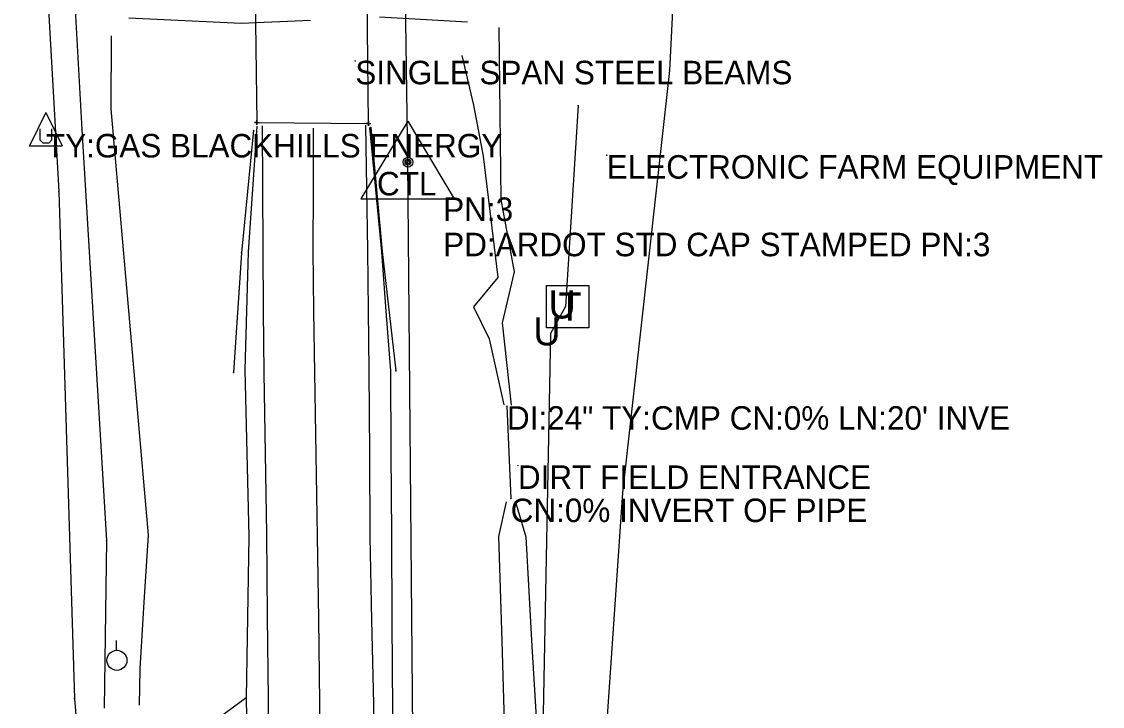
# Model space of a CAD drawing. Extents: x 1804576 to 1805329, y 515859 to 519427.
# Drawn here: x 1804889.4 to 1805119.1, y 517586 to 517731.6 of the extents above; entities that cross this region are included whole.
import ezdxf

# ---------------------------------------------------------------- set-up
doc = ezdxf.new("R2010")
doc.units = 0
for name, color, linetype in [('Default', 7, 'Continuous'), ('S_BASELINE', 7, 'Continuous'), ('S_BRIDGE', 7, 'Continuous'), ('S_DITCHLINE', 7, 'Continuous'), ('S_DRG_PT_SYM', 7, 'Continuous'), ('S_EDGE_PAVEMENT', 7, 'Continuous'), ('S_FIBER_OPTIC_CABLE', 7, 'Continuous'), ('S_GAS_UTILITIES', 7, 'Continuous'), ('S_GUARDRAIL', 7, 'Continuous'), ('S_MISC_STRUCTURES_ANNOT', 7, 'Continuous'), ('S_MSC_PT_SYM', 7, 'Continuous'), ('S_PAVEMENT_CROWN', 7, 'Continuous'), ('S_PRIMARY_CTL', 7, 'Continuous'), ('S_PRIMARY_CTL_ANNOT', 7, 'Continuous'), ('S_RDW_PT_SYM', 7, 'Continuous'), ('S_SHOULDER', 7, 'Continuous'), ('S_SIDE_DRAIN', 7, 'Continuous'), ('S_SIDE_DRAIN_ANNOT', 7, 'Continuous'), ('S_STR_PT_SYM', 7, 'Continuous'), ('S_STREAM', 7, 'Continuous'), ('S_SURVEY_TEXT_ANNOT', 7, 'Continuous'), ('S_TELEPHONE_UTILITIES', 7, 'Continuous'), ('S_UNDERGROUND_CABLE', 7, 'Continuous'), ('S_UTILITY_POLE', 7, 'Continuous'), ('S_UTILITY_POLE_ANNOT', 7, 'Continuous'), ('S_UTL_PT_SYM', 7, 'Continuous'), ('S_WATER_UTILITIES', 7, 'Continuous')]:
    doc.layers.add(name, color=color, linetype=linetype)

msp = doc.modelspace()

# ---------------------------------------------------------------- linework, layer by layer
at = {"layer": 'S_BASELINE'}
for p, q in [((1804971.48, 517701.71), (1804956.7, 518650.01)), ((1804979.02, 516850.02), (1804971.48, 517701.71))]:
    msp.add_line(p, q, dxfattribs=at)
at = {"layer": 'S_BRIDGE'}
for p, q in [((1804963.12, 517709.92), (1804962.51, 517765.12)), ((1804938.7, 517764.9), (1804939.34, 517710.14)), ((1804939.34, 517710.14), (1804963.12, 517709.92))]:
    msp.add_line(p, q, dxfattribs=at)
at = {"layer": 'S_DITCHLINE'}
for points in [[(1804908.38, 517728.61), (1804908.3, 517713.03), (1804910.28, 517690.37), (1804912.27, 517667.7), (1804914.25, 517645.04), (1804916.23, 517622.38), (1804915.35, 517608.16), (1804914.48, 517593.93), (1804914.34, 517586.26)], [(1804993.51, 517650.05), (1804991.59, 517667.58), (1804994.15, 517678.37), (1804991.29, 517693.8), (1804991.07, 517712.08), (1804990.84, 517730.36)], [(1804982.94, 517724.38), (1804985.41, 517713.87), (1804987.46, 517703.03), (1804989.02, 517690.1), (1804990.58, 517677.17), (1804985.38, 517670.95), (1804988.71, 517664.18), (1804991.88, 517650.09)], [(1804992.34, 517629.48), (1804990.73, 517622.13), (1804991.4, 517599.91), (1804992.07, 517577.69), (1804991.26, 517563.34), (1804990.45, 517548.98), (1804989.64, 517534.63), (1804988.82, 517520.28), (1804988.18, 517498.42), (1804987.54, 517476.57), (1804986.98, 517462.63), (1804986.42, 517448.7), (1804985.86, 517434.77), (1804985.31, 517420.83), (1804985.82, 517401.34), (1804986.33, 517381.85)], [(1804994.29, 517629.66), (1804996.5, 517622.01), (1804997.84, 517598.75), (1804999.19, 517575.49), (1804996.83, 517561.75), (1804994.47, 517548), (1804992.11, 517534.26), (1804989.75, 517520.52), (1804988.99, 517498.56), (1804988.23, 517476.6), (1804987.73, 517462.59), (1804987.24, 517448.59), (1804986.75, 517434.59), (1804986.25, 517420.59), (1804986.64, 517401.2), (1804987.03, 517381.82)]]:
    msp.add_lwpolyline(points, dxfattribs=at)
at = {"layer": 'S_DRG_PT_SYM'}
for points in [[(1804992.52, 517649.82), (1804992.52, 517649.87), (1804992.52, 517649.82), (1804992.47, 517649.82), (1804992.52, 517649.82), (1804992.52, 517649.77), (1804992.52, 517649.82), (1804992.57, 517649.82)], [(1804993.31, 517630.17), (1804993.31, 517630.22), (1804993.31, 517630.17), (1804993.26, 517630.17), (1804993.31, 517630.17), (1804993.31, 517630.12), (1804993.31, 517630.17), (1804993.36, 517630.17)]]:
    msp.add_lwpolyline(points, dxfattribs=at)
at = {"layer": 'S_EDGE_PAVEMENT'}
for points in [[(1804940.46, 517709.42), (1804940.53, 517696.33), (1804940.61, 517683.24), (1804940.74, 517670.08), (1804940.88, 517656.93), (1804941.15, 517639.79), (1804941.42, 517622.66), (1804941.59, 517605.09), (1804941.76, 517587.51), (1804941.82, 517574.8), (1804941.89, 517562.09), (1804942.21, 517539.1), (1804942.54, 517516.11), (1804942.97, 517492.9), (1804943.39, 517469.69), (1804943.57, 517445.12), (1804943.76, 517420.54), (1804944.11, 517396.98), (1804944.47, 517373.41)], [(1804962.48, 517709.57), (1804962.67, 517696.25), (1804962.86, 517682.93), (1804963.02, 517670.14), (1804963.19, 517657.36), (1804963.3, 517639.71), (1804963.4, 517622.06), (1804963.76, 517604.29), (1804964.12, 517586.52), (1804964.31, 517564.57), (1804964.38, 517544.75), (1804964.45, 517524.93), (1804964.7, 517511.48), (1804964.95, 517498.03), (1804965.2, 517484.58), (1804965.45, 517471.12), (1804965.58, 517458.56), (1804965.7, 517445.99), (1804965.83, 517433.42), (1804965.96, 517420.85), (1804966.31, 517397.71), (1804966.66, 517374.58)], [(1804937.12, 517587.77), (1804929.82, 517582.39), (1804921.73, 517579.49), (1804914.51, 517578.77), (1804913.22, 517568.91), (1804921.24, 517568.04), (1804930.31, 517565.67), (1804937.46, 517562.48)]]:
    msp.add_lwpolyline(points, dxfattribs=at)
at = {"layer": 'S_FIBER_OPTIC_CABLE'}
for p, q in [((1804895.93, 517822.38), (1804902.15, 517708.69)), ((1805007.68, 517713.77), (1805004.99, 517671.01)), ((1804902.15, 517708.69), (1804907.42, 517621.23)), ((1805004.99, 517671.01), (1805001.76, 517665.3)), ((1805001.76, 517665.3), (1804999.7, 517558.11)), ((1804907.42, 517621.23), (1804906.91, 517585.58))]:
    msp.add_line(p, q, dxfattribs=at)
at = {"layer": 'S_GAS_UTILITIES'}
for p, q in [((1804889.37, 517837.53), (1804897.25, 517695.47)), ((1804897.25, 517695.47), (1804900.59, 517587.64)), ((1804900.59, 517587.64), (1804907.72, 517506.16))]:
    msp.add_line(p, q, dxfattribs=at)
at = {"layer": 'S_GUARDRAIL'}
for p, q in [((1804938.68, 517708.49), (1804936.1, 517682.44)), ((1804963.58, 517709.11), (1804965.97, 517682.7)), ((1804936.1, 517682.44), (1804934.39, 517656.96)), ((1804965.97, 517682.7), (1804968.9, 517657.34))]:
    msp.add_line(p, q, dxfattribs=at)
at = {"layer": 'S_MSC_PT_SYM'}
for points in [[(1804960.29, 517723.28), (1804960.29, 517723.33), (1804960.29, 517723.28), (1804960.24, 517723.28), (1804960.29, 517723.28), (1804960.29, 517723.23), (1804960.29, 517723.28), (1804960.34, 517723.28)], [(1805013.73, 517703.21), (1805013.73, 517703.26), (1805013.73, 517703.21), (1805013.68, 517703.21), (1805013.73, 517703.21), (1805013.73, 517703.16), (1805013.73, 517703.21), (1805013.78, 517703.21)], [(1804994.85, 517637.23), (1804994.85, 517637.28), (1804994.85, 517637.23), (1804994.8, 517637.23), (1804994.85, 517637.23), (1804994.85, 517637.18), (1804994.85, 517637.23), (1804994.9, 517637.23)]]:
    msp.add_lwpolyline(points, dxfattribs=at)
at = {"layer": 'S_PAVEMENT_CROWN'}
msp.add_lwpolyline([(1804951.35, 517708.92), (1804951.32, 517696), (1804951.29, 517683.08), (1804951.43, 517670), (1804951.58, 517656.91), (1804951.88, 517639.56), (1804952.18, 517622.21), (1804952.44, 517604.51), (1804952.7, 517586.81), (1804952.87, 517563.54), (1804953.18, 517539.97), (1804953.49, 517516.4), (1804953.89, 517493.53), (1804954.28, 517470.66), (1804954.4, 517458.04), (1804954.53, 517445.43), (1804954.65, 517432.82), (1804954.78, 517420.21), (1804955.07, 517396.93), (1804955.36, 517373.65)], dxfattribs=at)
at = {"layer": 'S_PRIMARY_CTL'}
for p, q in [((1804971.48, 517710.42), (1804961.45, 517693.9)), ((1804971.48, 517710.42), (1804981.31, 517693.9)), ((1804961.45, 517693.9), (1804981.31, 517693.9))]:
    msp.add_line(p, q, dxfattribs=at)
for radius in [1.04, 0.609, 0.344]:
    msp.add_circle((1804971.48, 517701.71), radius, dxfattribs=at)
at = {"layer": 'S_RDW_PT_SYM'}
for points in [[(1804938.68, 517708.49), (1804938.68, 517708.54), (1804938.68, 517708.49), (1804938.63, 517708.49), (1804938.68, 517708.49), (1804938.68, 517708.44), (1804938.68, 517708.49), (1804938.73, 517708.49)], [(1804963.58, 517709.11), (1804963.58, 517709.16), (1804963.58, 517709.11), (1804963.53, 517709.11), (1804963.58, 517709.11), (1804963.58, 517709.06), (1804963.58, 517709.11), (1804963.63, 517709.11)], [(1804936.1, 517682.44), (1804936.1, 517682.49), (1804936.1, 517682.44), (1804936.05, 517682.44), (1804936.1, 517682.44), (1804936.1, 517682.39), (1804936.1, 517682.44), (1804936.15, 517682.44)], [(1804965.97, 517682.7), (1804965.97, 517682.75), (1804965.97, 517682.7), (1804965.92, 517682.7), (1804965.97, 517682.7), (1804965.97, 517682.65), (1804965.97, 517682.7), (1804966.02, 517682.7)], [(1804934.39, 517656.96), (1804934.39, 517657.01), (1804934.39, 517656.96), (1804934.34, 517656.96), (1804934.39, 517656.96), (1804934.39, 517656.91), (1804934.39, 517656.96), (1804934.44, 517656.96)], [(1804968.9, 517657.34), (1804968.9, 517657.39), (1804968.9, 517657.34), (1804968.85, 517657.34), (1804968.9, 517657.34), (1804968.9, 517657.29), (1804968.9, 517657.34), (1804968.95, 517657.34)]]:
    msp.add_lwpolyline(points, dxfattribs=at)
at = {"layer": 'S_SHOULDER'}
for points in [[(1804939.34, 517709.36), (1804938.44, 517696.01), (1804937.54, 517682.66), (1804937.19, 517670.12), (1804936.83, 517657.58), (1804937.23, 517639.85), (1804937.63, 517622.12), (1804937.37, 517604.95), (1804937.12, 517587.79), (1804937.29, 517575.12), (1804937.45, 517562.46), (1804938.01, 517539.37), (1804938.57, 517516.27), (1804938.84, 517492.83), (1804939.1, 517469.39), (1804939.28, 517445.13), (1804939.46, 517420.88), (1804939.67, 517396.64), (1804939.87, 517372.4)], [(1804963.34, 517709.11), (1804964.59, 517695.88), (1804965.85, 517682.65), (1804966.81, 517670), (1804967.78, 517657.34), (1804967.87, 517639.95), (1804967.96, 517622.56), (1804968.08, 517603.88), (1804968.2, 517585.21), (1804968.75, 517563.81), (1804969, 517539.98), (1804969.26, 517516.16), (1804969.52, 517493.79), (1804969.79, 517471.42), (1804969.98, 517458.76), (1804970.17, 517446.09), (1804970.36, 517433.42), (1804970.55, 517420.76), (1804970.85, 517398.22), (1804971.15, 517375.69)]]:
    msp.add_lwpolyline(points, dxfattribs=at)
at = {"layer": 'S_SIDE_DRAIN'}
msp.add_line((1804992.52, 517649.82), (1804993.31, 517630.17), dxfattribs=at)
at = {"layer": 'S_STR_PT_SYM'}
for points in [[(1804939.34, 517710.14), (1804939.34, 517710.64), (1804939.34, 517710.14), (1804938.84, 517710.14), (1804939.34, 517710.14), (1804939.34, 517709.64), (1804939.34, 517710.14), (1804939.84, 517710.14)], [(1804963.12, 517709.92), (1804963.12, 517710.42), (1804963.12, 517709.92), (1804962.62, 517709.92), (1804963.12, 517709.92), (1804963.12, 517709.42), (1804963.12, 517709.92), (1804963.62, 517709.92)]]:
    msp.add_lwpolyline(points, dxfattribs=at)
at = {"layer": 'S_STREAM'}
for points in [[(1804950.73, 517731.88), (1804936.03, 517731.18), (1804912.17, 517732.34)], [(1804984.11, 517731.52), (1804965.43, 517732.59)]]:
    msp.add_lwpolyline(points, dxfattribs=at)
at = {"layer": 'S_TELEPHONE_UTILITIES'}
msp.add_lwpolyline([(1805000.89, 517666.52), (1805000.89, 517675.52), (1805009.89, 517675.52), (1805009.89, 517666.52)], close=True, dxfattribs=at)
at = {"layer": 'S_UNDERGROUND_CABLE'}
for p, q in [((1804894.54, 517712.25), (1804891.01, 517705.16)), ((1804894.54, 517712.25), (1804898.02, 517705.16)), ((1804893.34, 517706.4), (1804893.34, 517708.84)), ((1804895.7, 517708.84), (1804895.7, 517706.4)), ((1804893.96, 517705.74), (1804893.34, 517706.4)), ((1804895.16, 517705.74), (1804893.96, 517705.74)), ((1804895.7, 517706.4), (1804895.16, 517705.74)), ((1804891.01, 517705.16), (1804898.02, 517705.16))]:
    msp.add_line(p, q, dxfattribs=at)
at = {"layer": 'S_UTILITY_POLE'}
msp.add_line((1804909.5, 517597.91), (1804909.5, 517600.01), dxfattribs=at)
msp.add_circle((1804909.62, 517595.77), 2.13, dxfattribs=at)
at = {"layer": 'S_UTL_PT_SYM'}
for points in [[(1805027.1, 517721.24), (1805027.1, 517721.29), (1805027.1, 517721.24), (1805027.05, 517721.24), (1805027.1, 517721.24), (1805027.1, 517721.19), (1805027.1, 517721.24), (1805027.15, 517721.24)], [(1805007.68, 517713.77), (1805007.68, 517713.82), (1805007.68, 517713.77), (1805007.63, 517713.77), (1805007.68, 517713.77), (1805007.68, 517713.72), (1805007.68, 517713.77), (1805007.73, 517713.77)], [(1804902.15, 517708.69), (1804902.15, 517708.74), (1804902.15, 517708.69), (1804902.1, 517708.69), (1804902.15, 517708.69), (1804902.15, 517708.64), (1804902.15, 517708.69), (1804902.2, 517708.69)], [(1804897.25, 517695.47), (1804897.25, 517695.52), (1804897.25, 517695.47), (1804897.2, 517695.47), (1804897.25, 517695.47), (1804897.25, 517695.42), (1804897.25, 517695.47), (1804897.3, 517695.47)], [(1805017.05, 517631.36), (1805017.05, 517631.41), (1805017.05, 517631.36), (1805017, 517631.36), (1805017.05, 517631.36), (1805017.05, 517631.31), (1805017.05, 517631.36), (1805017.1, 517631.36)], [(1804907.42, 517621.23), (1804907.42, 517621.28), (1804907.42, 517621.23), (1804907.37, 517621.23), (1804907.42, 517621.23), (1804907.42, 517621.18), (1804907.42, 517621.23), (1804907.47, 517621.23)], [(1804900.59, 517587.64), (1804900.59, 517587.69), (1804900.59, 517587.64), (1804900.54, 517587.64), (1804900.59, 517587.64), (1804900.59, 517587.59), (1804900.59, 517587.64), (1804900.64, 517587.64)]]:
    msp.add_lwpolyline(points, dxfattribs=at)
at = {"layer": 'S_WATER_UTILITIES'}
for p, q in [((1805029.04, 517763.32), (1805027.1, 517721.24)), ((1805027.1, 517721.24), (1805017.05, 517631.36)), ((1805017.05, 517631.36), (1805006.45, 517476.66))]:
    msp.add_line(p, q, dxfattribs=at)

# ---------------------------------------------------------------- texts
at = {"layer": 'Default'}
for p in [(1805001.36, 517668.47), (1804998.13, 517662.75)]:
    msp.add_text('U', height=6, dxfattribs=at).set_placement(p)
at = {"layer": 'S_MISC_STRUCTURES_ANNOT'}
msp.add_text('ELECTRONIC FARM EQUIPMENT', height=5, dxfattribs=at).set_placement((1805013.73, 517698.21))
at = {"layer": 'S_PRIMARY_CTL'}
msp.add_text('CTL', height=5, dxfattribs=at).set_placement((1804964.9, 517694.64))
at = {"layer": 'S_PRIMARY_CTL_ANNOT'}
for s, p in [('PN:3', (1804978.98, 517689.21)), ('PD:ARDOT STD CAP STAMPED PN:3', (1804978.98, 517681.71))]:
    msp.add_text(s, height=5, dxfattribs=at).set_placement(p)
at = {"layer": 'S_SIDE_DRAIN_ANNOT'}
for s, p in [('DI:24" TY:CMP CN:0% LN:20\' INVE', (1804992.52, 517644.82)), ('CN:0% INVERT OF PIPE', (1804993.31, 517625.17))]:
    msp.add_text(s, height=5, dxfattribs=at).set_placement(p)
at = {"layer": 'S_SURVEY_TEXT_ANNOT'}
for s, p in [('SINGLE SPAN STEEL BEAMS', (1804960.29, 517718.28)), ('DIRT FIELD ENTRANCE', (1804994.85, 517632.23))]:
    msp.add_text(s, height=5, dxfattribs=at).set_placement(p)
at = {"layer": 'S_TELEPHONE_UTILITIES'}
msp.add_text('T', height=6, dxfattribs=at).set_placement((1805003.45, 517668.02))
at = {"layer": 'S_UTILITY_POLE_ANNOT'}
msp.add_text('TY:GAS BLACKHILLS ENERGY', height=5, dxfattribs=at).set_placement((1804894.54, 517702.72))

doc.saveas('drawing.dxf')
